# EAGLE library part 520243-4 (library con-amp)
AMP connector
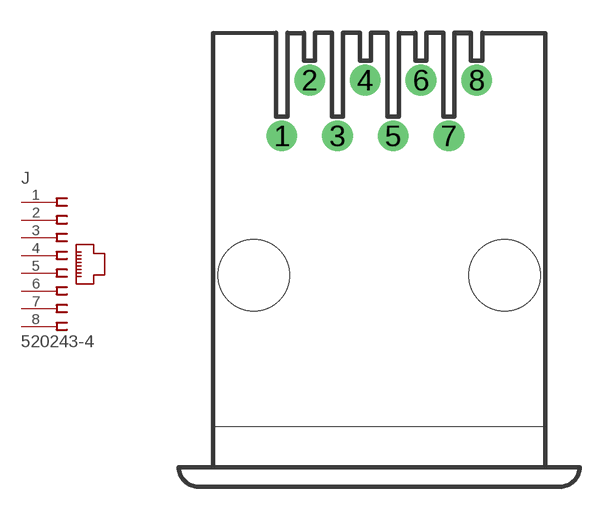
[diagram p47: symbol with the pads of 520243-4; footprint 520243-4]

Designator prefix J

## 520243-4 (MF: TYCO ELECTRONICS; MPN: 5520243-4; OC_FARNELL: unknown; OC_NEWARK: 42K7220)  [520243-4]
1  1  pas
2  2  pas
3  3  pas
4  4  pas
5  5  pas
6  6  pas
7  7  pas
8  8  pas

## Footprint 520243-4 (pad centres in mm)
Modular Jack with Flanged
drill 0.889 round: 1 -4.445,6.35; 2 -3.175,8.89; 3 -1.905,6.35; 4 -0.635,8.89; 5 0.635,6.35; 6 1.905,8.89; 7 3.175,6.35; 8 4.445,8.89
hole 3.251 at -5.715,0
hole 3.251 at 5.715,0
